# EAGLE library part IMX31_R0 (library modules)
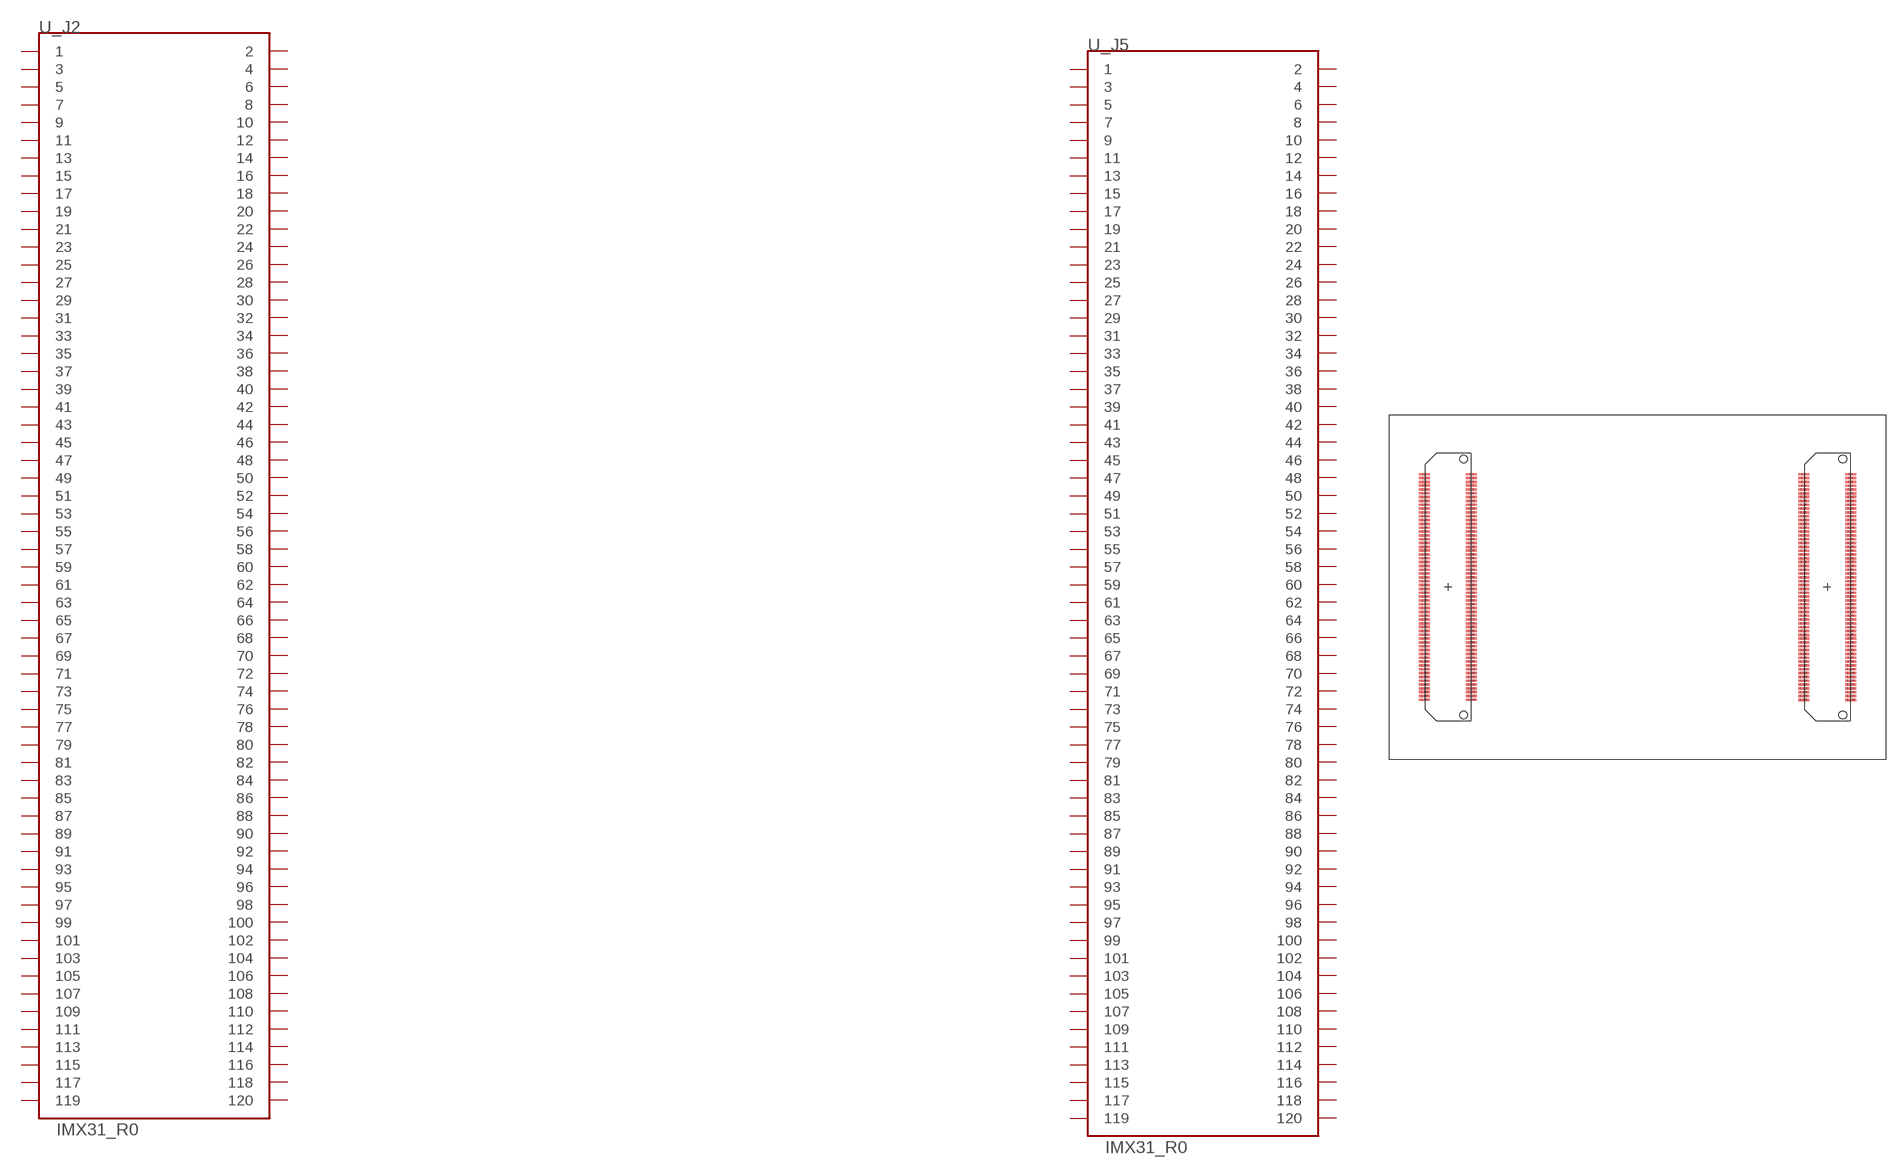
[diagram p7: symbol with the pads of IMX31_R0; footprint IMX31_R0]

Designator prefix -; gates _J2=120PINS-BTB-CONNECTOR _J5=120PINS-BTB-CONNECTOR

## IMX31_R0  [IMX31_R0]
1_1  _J2:1
1_2  _J2:2
1_3  _J2:3
1_4  _J2:4
1_5  _J2:5
1_6  _J2:6
1_7  _J2:7
1_8  _J2:8
1_9  _J2:9
1_10  _J2:10
1_11  _J2:11
1_12  _J2:12
1_13  _J2:13
1_14  _J2:14
1_15  _J2:15
1_16  _J2:16
1_17  _J2:17
1_18  _J2:18
1_19  _J2:19
1_20  _J2:20
1_21  _J2:21
1_22  _J2:22
1_23  _J2:23
1_24  _J2:24
1_25  _J2:25
1_26  _J2:26
1_27  _J2:27
1_28  _J2:28
1_29  _J2:29
1_30  _J2:30
1_31  _J2:31
1_32  _J2:32
1_33  _J2:33
1_34  _J2:34
1_35  _J2:35
1_36  _J2:36
1_37  _J2:37
1_38  _J2:38
1_39  _J2:39
1_40  _J2:40
1_41  _J2:41
1_42  _J2:42
1_43  _J2:43
1_44  _J2:44
1_45  _J2:45
1_46  _J2:46
1_47  _J2:47
1_48  _J2:48
1_49  _J2:49
1_50  _J2:50
1_51  _J2:51
1_52  _J2:52
1_53  _J2:53
1_54  _J2:54
1_55  _J2:55
1_56  _J2:56
1_57  _J2:57
1_58  _J2:58
1_59  _J2:59
1_60  _J2:60
1_61  _J2:61
1_62  _J2:62
1_63  _J2:63
1_64  _J2:64
1_65  _J2:65
1_66  _J2:66
1_67  _J2:67
1_68  _J2:68
1_69  _J2:69
1_70  _J2:70
1_71  _J2:71
1_72  _J2:72
1_73  _J2:73
1_74  _J2:74
1_75  _J2:75
1_76  _J2:76
1_77  _J2:77
1_78  _J2:78
1_79  _J2:79
1_80  _J2:80
1_81  _J2:81
1_82  _J2:82
1_83  _J2:83
1_84  _J2:84
1_85  _J2:85
1_86  _J2:86
1_87  _J2:87
1_88  _J2:88
1_89  _J2:89
1_90  _J2:90
1_91  _J2:91
1_92  _J2:92
1_93  _J2:93
1_94  _J2:94
1_95  _J2:95
1_96  _J2:96
1_97  _J2:97
1_98  _J2:98
1_99  _J2:99
1_100  _J2:100
1_101  _J2:101
1_102  _J2:102
1_103  _J2:103
1_104  _J2:104
1_105  _J2:105
1_106  _J2:106
1_107  _J2:107
1_108  _J2:108
1_109  _J2:109
1_110  _J2:110
1_111  _J2:111
1_112  _J2:112
1_113  _J2:113
1_114  _J2:114
1_115  _J2:115
1_116  _J2:116
1_117  _J2:117
1_118  _J2:118
1_119  _J2:119
1_120  _J2:120
2_1  _J5:1
2_2  _J5:2
2_3  _J5:3
2_4  _J5:4
2_5  _J5:5
2_6  _J5:6
2_7  _J5:7
2_8  _J5:8
2_9  _J5:9
2_10  _J5:10
2_11  _J5:11
2_12  _J5:12
2_13  _J5:13
2_14  _J5:14
2_15  _J5:15
2_16  _J5:16
2_17  _J5:17
2_18  _J5:18
2_19  _J5:19
2_20  _J5:20
2_21  _J5:21
2_22  _J5:22
2_23  _J5:23
2_24  _J5:24
2_25  _J5:25
2_26  _J5:26
2_27  _J5:27
2_28  _J5:28
2_29  _J5:29
2_30  _J5:30
2_31  _J5:31
2_32  _J5:32
2_33  _J5:33
2_34  _J5:34
2_35  _J5:35
2_36  _J5:36
2_37  _J5:37
2_38  _J5:38
2_39  _J5:39
2_40  _J5:40
2_41  _J5:41
2_42  _J5:42
2_43  _J5:43
2_44  _J5:44
2_45  _J5:45
2_46  _J5:46
2_47  _J5:47
2_48  _J5:48
2_49  _J5:49
2_50  _J5:50
2_51  _J5:51
2_52  _J5:52
2_53  _J5:53
2_54  _J5:54
2_55  _J5:55
2_56  _J5:56
2_57  _J5:57
2_58  _J5:58
2_59  _J5:59
2_60  _J5:60
2_61  _J5:61
2_62  _J5:62
2_63  _J5:63
2_64  _J5:64
2_65  _J5:65
2_66  _J5:66
2_67  _J5:67
2_68  _J5:68
2_69  _J5:69
2_70  _J5:70
2_71  _J5:71
2_72  _J5:72
2_73  _J5:73
2_74  _J5:74
2_75  _J5:75
2_76  _J5:76
2_77  _J5:77
2_78  _J5:78
2_79  _J5:79
2_80  _J5:80
2_81  _J5:81
2_82  _J5:82
2_83  _J5:83
2_84  _J5:84
2_85  _J5:85
2_86  _J5:86
2_87  _J5:87
2_88  _J5:88
2_89  _J5:89
2_90  _J5:90
2_91  _J5:91
2_92  _J5:92
2_93  _J5:93
2_94  _J5:94
2_95  _J5:95
2_96  _J5:96
2_97  _J5:97
2_98  _J5:98
2_99  _J5:99
2_100  _J5:100
2_101  _J5:101
2_102  _J5:102
2_103  _J5:103
2_104  _J5:104
2_105  _J5:105
2_106  _J5:106
2_107  _J5:107
2_108  _J5:108
2_109  _J5:109
2_110  _J5:110
2_111  _J5:111
2_112  _J5:112
2_113  _J5:113
2_114  _J5:114
2_115  _J5:115
2_116  _J5:116
2_117  _J5:117
2_118  _J5:118
2_119  _J5:119
2_120  _J5:120

## Footprint IMX31_R0 (pad centres in mm)
CT: 6 oct. 2008: changed drill of locking pins to 0.04" according to datasheet of -A option of connectors.
smd 1.448 x 0.305: 1_1 -21.714,14.755; 1_2 -27.886,14.755; 1_3 -21.714,14.255; 1_4 -27.886,14.255; 1_5 -21.714,13.755; 1_6 -27.886,13.755; 1_7 -21.714,13.255; 1_8 -27.886,13.255; 1_9 -21.714,12.755; 1_10 -27.886,12.755; 1_11 -21.714,12.255; 1_12 -27.886,12.255; 1_13 -21.714,11.755; 1_14 -27.886,11.755; 1_15 -21.714,11.255; 1_16 -27.886,11.255; 1_17 -21.714,10.755; 1_18 -27.886,10.755; 1_19 -21.714,10.255; 1_20 -27.886,10.255; 1_21 -21.714,9.755; 1_22 -27.886,9.755; 1_23 -21.714,9.255; 1_24 -27.886,9.255; 1_25 -21.714,8.755; 1_26 -27.886,8.755; 1_27 -21.714,8.255; 1_28 -27.886,8.255; 1_29 -21.714,7.755; 1_30 -27.886,7.755; 1_31 -21.714,7.255; 1_32 -27.886,7.255; 1_33 -21.714,6.755; 1_34 -27.886,6.755; 1_35 -21.714,6.255; 1_36 -27.886,6.255; 1_37 -21.714,5.755; 1_38 -27.886,5.755; 1_39 -21.714,5.255; 1_40 -27.886,5.255; 1_41 -21.714,4.755; 1_42 -27.886,4.755; 1_43 -21.714,4.255; 1_44 -27.886,4.255; 1_45 -21.714,3.755; 1_46 -27.886,3.755; 1_47 -21.714,3.255; 1_48 -27.886,3.255; 1_49 -21.714,2.755; 1_50 -27.886,2.755; 1_51 -21.714,2.255; 1_52 -27.886,2.255; 1_53 -21.714,1.755; 1_54 -27.886,1.755; 1_55 -21.714,1.255; 1_56 -27.886,1.255; 1_57 -21.714,0.755; 1_58 -27.886,0.755; 1_59 -21.714,0.255; 1_60 -27.886,0.255; 1_61 -21.714,-0.248; 1_62 -27.886,-0.248; 1_63 -21.714,-0.748; 1_64 -27.886,-0.748; 1_65 -21.714,-1.248; 1_66 -27.886,-1.248; 1_67 -21.714,-1.748; 1_68 -27.886,-1.748; 1_69 -21.714,-2.248; 1_70 -27.886,-2.248; 1_71 -21.714,-2.748; 1_72 -27.886,-2.748; 1_73 -21.714,-3.248; 1_74 -27.886,-3.248; 1_75 -21.714,-3.748; 1_76 -27.886,-3.748; 1_77 -21.714,-4.248; 1_78 -27.886,-4.248; 1_79 -21.714,-4.748; 1_80 -27.886,-4.748; 1_81 -21.714,-5.248; 1_82 -27.886,-5.248; 1_83 -21.714,-5.748; 1_84 -27.886,-5.748; 1_85 -21.714,-6.248; 1_86 -27.886,-6.248; 1_87 -21.714,-6.748; 1_88 -27.886,-6.748; 1_89 -21.714,-7.248; 1_90 -27.886,-7.248; 1_91 -21.714,-7.748; 1_92 -27.886,-7.748; 1_93 -21.714,-8.248; 1_94 -27.886,-8.248; 1_95 -21.714,-8.748; 1_96 -27.886,-8.748; 1_97 -21.714,-9.248; 1_98 -27.886,-9.248; 1_99 -21.714,-9.748; 1_100 -27.886,-9.748; 1_101 -21.714,-10.248; 1_102 -27.886,-10.248; 1_103 -21.714,-10.748; 1_104 -27.886,-10.748; 1_105 -21.714,-11.248; 1_106 -27.886,-11.248; 1_107 -21.714,-11.748; 1_108 -27.886,-11.748; 1_109 -21.714,-12.248; 1_110 -27.886,-12.248; 1_111 -21.714,-12.748; 1_112 -27.886,-12.748; 1_113 -21.714,-13.248; 1_114 -27.886,-13.248; 1_115 -21.714,-13.748; 1_116 -27.886,-13.748; 1_117 -21.714,-14.248; 1_118 -27.886,-14.248; 1_119 -21.714,-14.748; 1_120 -27.886,-14.748; 2_1 27.885,14.752; 2_2 21.713,14.752; 2_3 27.885,14.252; 2_4 21.713,14.252; 2_5 27.885,13.752; 2_6 21.713,13.752; 2_7 27.885,13.252; 2_8 21.713,13.252; 2_9 27.885,12.752; 2_10 21.713,12.752; 2_11 27.885,12.252; 2_12 21.713,12.252; 2_13 27.885,11.752; 2_14 21.713,11.752; 2_15 27.885,11.252; 2_16 21.713,11.252; 2_17 27.885,10.752; 2_18 21.713,10.752; 2_19 27.885,10.252; 2_20 21.713,10.252; 2_21 27.885,9.752; 2_22 21.713,9.752; 2_23 27.885,9.252; 2_24 21.713,9.252; 2_25 27.885,8.752; 2_26 21.713,8.752; 2_27 27.885,8.252; 2_28 21.713,8.252; 2_29 27.885,7.752; 2_30 21.713,7.752; 2_31 27.885,7.252; 2_32 21.713,7.252; 2_33 27.885,6.752; 2_34 21.713,6.752; 2_35 27.885,6.252; 2_36 21.713,6.252; 2_37 27.885,5.752; 2_38 21.713,5.752; 2_39 27.885,5.252; 2_40 21.713,5.252; 2_41 27.885,4.752; 2_42 21.713,4.752; 2_43 27.885,4.252; 2_44 21.713,4.252; 2_45 27.885,3.752; 2_46 21.713,3.752; 2_47 27.885,3.251; 2_48 21.713,3.251; 2_49 27.885,2.751; 2_50 21.713,2.751; 2_51 27.885,2.251; 2_52 21.713,2.251; 2_53 27.885,1.752; 2_54 21.713,1.752; 2_55 27.885,1.252; 2_56 21.713,1.252; 2_57 27.885,0.751; 2_58 21.713,0.751; 2_59 27.885,0.252; 2_60 21.713,0.252; 2_61 27.885,-0.252; 2_62 21.713,-0.252; 2_63 27.884,-0.754; 2_64 21.713,-0.751; 2_65 27.885,-1.252; 2_66 21.713,-1.252; 2_67 27.885,-1.752; 2_68 21.713,-1.752; 2_69 27.885,-2.252; 2_70 21.713,-2.252; 2_71 27.885,-2.752; 2_72 21.713,-2.752; 2_73 27.885,-3.252; 2_74 21.713,-3.252; 2_75 27.885,-3.752; 2_76 21.713,-3.752; 2_77 27.885,-4.252; 2_78 21.713,-4.252; 2_79 27.885,-4.752; 2_80 21.713,-4.752; 2_81 27.885,-5.252; 2_82 21.713,-5.252; 2_83 27.885,-5.752; 2_84 21.713,-5.752; 2_85 27.885,-6.252; 2_86 21.713,-6.252; 2_87 27.885,-6.752; 2_88 21.713,-6.752; 2_89 27.885,-7.252; 2_90 21.713,-7.252; 2_91 27.885,-7.752; 2_92 21.713,-7.752; 2_93 27.885,-8.252; 2_94 21.713,-8.252; 2_95 27.885,-8.752; 2_96 21.713,-8.752; 2_97 27.885,-9.252; 2_98 21.713,-9.252; 2_99 27.885,-9.752; 2_100 21.713,-9.752; 2_101 27.885,-10.252; 2_102 21.713,-10.252; 2_103 27.885,-10.752; 2_104 21.713,-10.752; 2_105 27.885,-11.252; 2_106 21.713,-11.252; 2_107 27.885,-11.752; 2_108 21.713,-11.752; 2_109 27.885,-12.252; 2_110 21.713,-12.252; 2_111 27.885,-12.752; 2_112 21.713,-12.752; 2_113 27.885,-13.252; 2_114 21.713,-13.252; 2_115 27.885,-13.752; 2_116 21.713,-13.752; 2_117 27.885,-14.252; 2_118 21.713,-14.252; 2_119 27.885,-14.752; 2_120 21.713,-14.752
hole 1.016 at -22.768,16.74
hole 1.016 at -22.768,-16.735
hole 1.016 at 26.831,16.736
hole 1.016 at 26.831,-16.739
